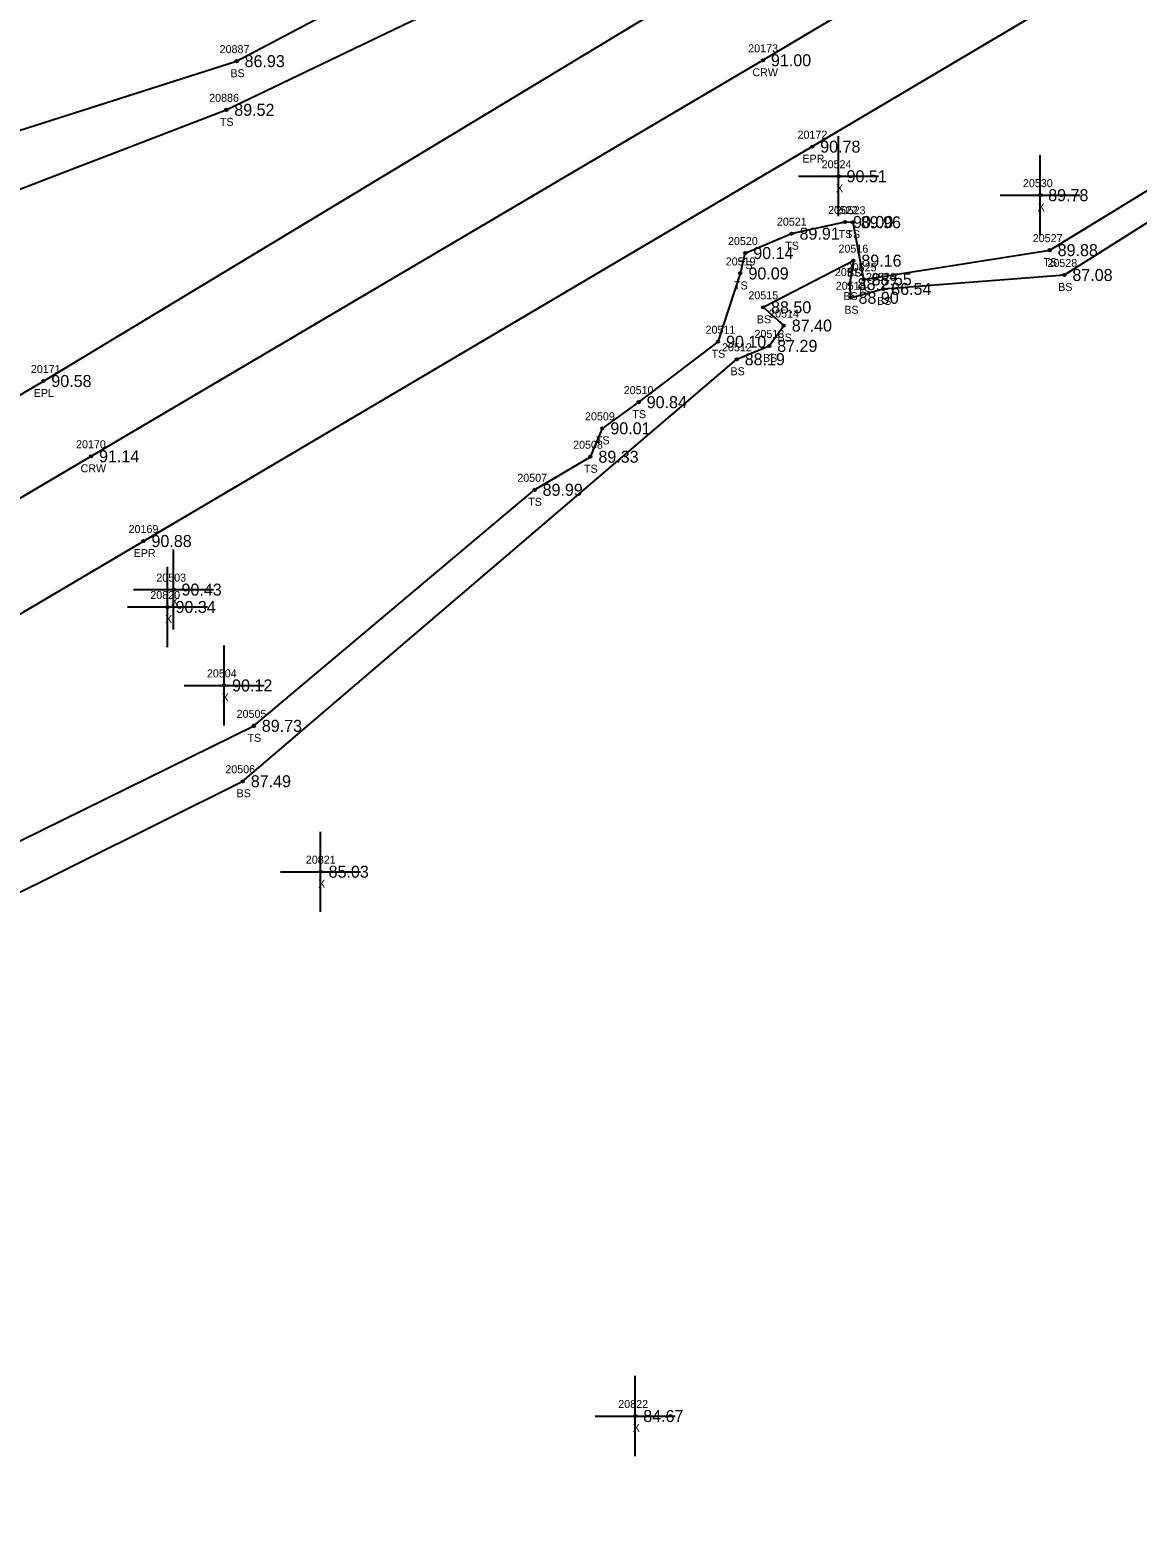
# Model space of a CAD drawing. Extents: x 2530197 to 2532051, y 935230 to 936631.
# Drawn here: x 2531374.5 to 2531512.9, y 935982 to 936167.6 of the extents above; entities that cross this region are included whole.
import ezdxf

# ---------------------------------------------------------------- set-up
doc = ezdxf.new("R2010")
doc.units = 0
for name, color, linetype in [('RD_DTM_BkLn1', 7, 'Continuous'), ('RD_DTM_BkLn2', 7, 'Continuous'), ('RD_DTM_BkLn_txCode', 7, 'Continuous'), ('RD_EX_Misc', 7, 'Continuous'), ('RD_EX_Misc_txCode', 7, 'Continuous'), ('RD_EX_Road', 7, 'Continuous'), ('RD_EX_Road_txCode', 7, 'Continuous'), ('RD_EX_TX_Misc_ELEV', 7, 'Continuous'), ('RD_EX_TX_Road_ELEV', 7, 'Continuous'), ('RD_HC_Survey_ELEV', 7, 'Continuous'), ('RD_HC_Survey_txCode', 7, 'Continuous'), ('RD_SMD_Locator', 7, 'Continuous')]:
    doc.layers.add(name, color=color, linetype=linetype)

msp = doc.modelspace()

# ---------------------------------------------------------------- linework, layer by layer
at = {"layer": 'RD_DTM_BkLn1'}
msp.add_lwpolyline([(2531175.16, 935992.09), (2531214.08, 936014.93), (2531297.2, 936064.16), (2531382.2, 936114.3), (2531466.12, 936163.77), (2531548.89, 936212.96), (2531632.55, 936261.89), (2531678, 936289.19), (2531722.34, 936315.93), (2531754.26, 936342.49), (2531759.78, 936349.83), (2531772.77, 936373.29), (2531778.96, 936389.71), (2531793.78, 936438.29), (2531813.65, 936511.36), (2531832.39, 936582.88)], dxfattribs=at)
at = {"layer": 'RD_DTM_BkLn2'}
for points in [[(2531232.8, 936067.46), (2531281.18, 936092.01), (2531356.28, 936135.72), (2531362.71, 936151.65), (2531400.38, 936163.66), (2531430.03, 936179.35), (2531446.05, 936177.07), (2531452.65, 936188.16), (2531481.32, 936210.45), (2531494.44, 936219.29)], [(2531229.61, 936049.23), (2531287.21, 936081.23), (2531360.99, 936124.94), (2531368.39, 936145.81), (2531399.09, 936157.58), (2531431.15, 936172.97), (2531448.86, 936171.41), (2531455.43, 936183.06), (2531483.94, 936207.52), (2531496.93, 936216.06)], [(2531295.18, 936026.12), (2531312.3, 936036.23), (2531402.53, 936080.62), (2531437.6, 936110.11), (2531444.57, 936114.24), (2531446.06, 936117.79), (2531450.6, 936121.06), (2531460.51, 936128.61), (2531463.31, 936137.14), (2531463.91, 936139.69), (2531469.69, 936142.11), (2531476.37, 936143.57), (2531477.33, 936143.53), (2531478.69, 936136.4), (2531501.93, 936140.05), (2531521.67, 936152.11)], [(2531295.18, 936026.12), (2531317.6, 936032.12), (2531401.15, 936073.7), (2531462.84, 936126.42), (2531466.9, 936128.09), (2531468.72, 936130.63), (2531466.13, 936132.91), (2531477.41, 936138.74), (2531476.94, 936135.81), (2531477.06, 936134.1), (2531481.14, 936135.21), (2531503.77, 936136.95), (2531524.91, 936150.29)]]:
    msp.add_lwpolyline(points, dxfattribs=at)
at = {"layer": 'RD_EX_Misc'}
for p, q in [((2531475.56, 936144.28), (2531475.56, 936154.28)), ((2531500.75, 936141.92), (2531500.75, 936151.92)), ((2531470.56, 936149.28), (2531480.56, 936149.28)), ((2531495.75, 936146.92), (2531505.75, 936146.92)), ((2531392.5, 936092.64), (2531392.5, 936102.64)), ((2531391.75, 936090.47), (2531391.75, 936100.47)), ((2531387.5, 936097.64), (2531397.5, 936097.64)), ((2531386.75, 936095.47), (2531396.75, 936095.47)), ((2531398.82, 936080.67), (2531398.82, 936090.67)), ((2531393.82, 936085.67), (2531403.82, 936085.67)), ((2531410.87, 936057.4), (2531410.87, 936067.4)), ((2531405.87, 936062.4), (2531415.87, 936062.4)), ((2531450.17, 935989.4), (2531450.17, 935999.4)), ((2531445.17, 935994.4), (2531455.17, 935994.4))]:
    msp.add_line(p, q, dxfattribs=at)
at = {"layer": 'RD_EX_Road'}
for points in [[(2531169.65, 936000.77), (2531208.79, 936024.95), (2531292.04, 936074.02), (2531376.24, 936123.7), (2531460.37, 936174.49), (2531542.92, 936223.44), (2531626.67, 936270.85), (2531672.4, 936298.39), (2531714.28, 936327.21), (2531747.19, 936360.45), (2531761.42, 936377.32), (2531773.11, 936411.11), (2531782.2, 936441.65), (2531803.17, 936514.76), (2531820.28, 936585.8)], [(2531180.82, 935982), (2531220.82, 936004.21), (2531303.54, 936053.39), (2531388.75, 936103.71), (2531472.27, 936152.98), (2531554.79, 936201.9), (2531638.11, 936250.92), (2531683.19, 936278.28), (2531730.37, 936304.55), (2531771.5, 936341.26), (2531788.67, 936375.53), (2531805.57, 936434.84), (2531825.53, 936508.74), (2531844.13, 936579.65)]]:
    msp.add_lwpolyline(points, dxfattribs=at)
at = {"layer": 'RD_SMD_Locator'}
for centre in [(2531400.38, 936163.66), (2531466.12, 936163.77), (2531399.09, 936157.58), (2531472.27, 936152.98), (2531475.56, 936149.28), (2531500.75, 936146.92), (2531476.37, 936143.57), (2531477.33, 936143.53), (2531469.69, 936142.11), (2531463.91, 936139.69), (2531477.41, 936138.74), (2531501.93, 936140.05), (2531463.31, 936137.14), (2531503.77, 936136.95), (2531476.94, 936135.81), (2531478.69, 936136.4), (2531481.14, 936135.21), (2531466.13, 936132.91), (2531477.06, 936134.1), (2531468.72, 936130.63), (2531460.51, 936128.61), (2531466.9, 936128.09), (2531462.84, 936126.42), (2531376.24, 936123.7), (2531450.6, 936121.06), (2531446.06, 936117.79), (2531382.2, 936114.3), (2531444.57, 936114.24), (2531437.6, 936110.11), (2531388.75, 936103.71), (2531392.5, 936097.64), (2531391.75, 936095.47), (2531398.82, 936085.67), (2531402.53, 936080.62), (2531401.15, 936073.7), (2531410.87, 936062.4), (2531450.17, 935994.4)]:
    msp.add_circle(centre, 0.15, dxfattribs=at)

# ---------------------------------------------------------------- texts
at = {"layer": 'RD_DTM_BkLn_txCode'}
for s, p in [('20887', (2531398.26, 936164.66)), ('BS', (2531399.6, 936161.66)), ('20886', (2531396.95, 936158.58)), ('TS', (2531398.29, 936155.58)), ('20522', (2531474.25, 936144.57)), ('20523', (2531475.21, 936144.53)), ('20521', (2531467.86, 936143.11)), ('TS', (2531475.58, 936141.57)), ('TS', (2531476.54, 936141.53)), ('20520', (2531461.75, 936140.69)), ('TS', (2531468.9, 936140.11)), ('20516', (2531475.55, 936139.74)), ('20527', (2531499.82, 936141.05)), ('20519', (2531461.47, 936138.14)), ('TS', (2531463.11, 936137.69)), ('TS', (2531501.14, 936138.05)), ('20528', (2531501.65, 936137.95)), ('20517', (2531475.1, 936136.81)), ('20525', (2531476.58, 936137.4)), ('BS', (2531476.63, 936136.74)), ('20526', (2531478.99, 936136.21)), ('TS', (2531462.51, 936135.14)), ('20515', (2531464.3, 936133.91)), ('20518', (2531475.22, 936135.1)), ('TS', (2531477.9, 936134.4)), ('BS', (2531502.99, 936134.95)), ('BS', (2531476.16, 936133.81)), ('BS', (2531476.28, 936132.1)), ('BS', (2531480.36, 936133.21)), ('BS', (2531465.35, 936130.91)), ('20514', (2531466.89, 936131.63)), ('20511', (2531458.95, 936129.61)), ('20513', (2531465.06, 936129.09)), ('BS', (2531467.94, 936128.63)), ('TS', (2531459.71, 936126.61)), ('20512', (2531461.01, 936127.42)), ('BS', (2531466.12, 936126.09)), ('BS', (2531462.06, 936124.42)), ('20510', (2531448.73, 936122.06)), ('TS', (2531449.81, 936119.06)), ('20509', (2531443.9, 936118.79)), ('TS', (2531445.26, 936115.79)), ('20508', (2531442.41, 936115.24)), ('TS', (2531443.77, 936112.24)), ('20507', (2531435.44, 936111.11)), ('TS', (2531436.8, 936108.11)), ('20505', (2531400.38, 936081.62)), ('TS', (2531401.74, 936078.62)), ('20506', (2531398.97, 936074.7)), ('BS', (2531400.38, 936071.7))]:
    msp.add_text(s, height=1, dxfattribs=at).set_placement(p)
at = {"layer": 'RD_EX_Misc_txCode'}
for s, p in [('20524', (2531473.45, 936150.28)), ('X', (2531475.25, 936147.28)), ('20530', (2531498.59, 936147.92)), ('X', (2531500.43, 936144.92)), ('20503', (2531390.35, 936098.64)), ('20820', (2531389.6, 936096.47)), ('X', (2531392.19, 936095.64)), ('X', (2531391.44, 936093.47)), ('20504', (2531396.67, 936086.67)), ('X', (2531398.51, 936083.67)), ('20821', (2531409.03, 936063.4)), ('X', (2531410.55, 936060.4)), ('20822', (2531448.05, 935995.4)), ('X', (2531449.85, 935992.4))]:
    msp.add_text(s, height=1, dxfattribs=at).set_placement(p)
at = {"layer": 'RD_EX_Road_txCode'}
for s, p in [('20172', (2531470.44, 936153.98)), ('EPR', (2531471.04, 936150.98)), ('20171', (2531374.68, 936124.7)), ('EPL', (2531375.03, 936121.7)), ('20169', (2531386.89, 936104.71)), ('EPR', (2531387.52, 936101.71))]:
    msp.add_text(s, height=1, dxfattribs=at).set_placement(p)
at = {"layer": 'RD_EX_TX_Misc_ELEV'}
for s, p in [('86.93', (2531401.38, 936162.91)), ('89.52', (2531400.09, 936156.83)), ('90.51', (2531476.56, 936148.53)), ('89.78', (2531501.75, 936146.17)), ('90.00', (2531477.37, 936142.82)), ('89.96', (2531478.33, 936142.78)), ('89.91', (2531470.69, 936141.36)), ('89.88', (2531502.93, 936139.3)), ('90.14', (2531464.91, 936138.94)), ('89.16', (2531478.41, 936137.99)), ('90.09', (2531464.31, 936136.39)), ('88.55', (2531479.69, 936135.65)), ('87.08', (2531504.77, 936136.2)), ('88.27', (2531477.94, 936135.06)), ('86.54', (2531482.14, 936134.46)), ('88.50', (2531467.13, 936132.16)), ('88.90', (2531478.06, 936133.35)), ('87.40', (2531469.72, 936129.88)), ('90.10', (2531461.51, 936127.86)), ('87.29', (2531467.9, 936127.34)), ('88.19', (2531463.84, 936125.67)), ('90.84', (2531451.6, 936120.31)), ('90.01', (2531447.06, 936117.04)), ('89.33', (2531445.57, 936113.49)), ('89.99', (2531438.6, 936109.36)), ('90.43', (2531393.5, 936096.89)), ('90.34', (2531392.75, 936094.72)), ('90.12', (2531399.82, 936084.92)), ('89.73', (2531403.53, 936079.87)), ('87.49', (2531402.15, 936072.95)), ('85.03', (2531411.87, 936061.65)), ('84.67', (2531451.17, 935993.65))]:
    msp.add_text(s, height=1.5, dxfattribs=at).set_placement(p)
at = {"layer": 'RD_EX_TX_Road_ELEV'}
for s, p in [('90.78', (2531473.27, 936152.23)), ('90.58', (2531377.24, 936122.95)), ('90.88', (2531389.75, 936102.96))]:
    msp.add_text(s, height=1.5, dxfattribs=at).set_placement(p)
at = {"layer": 'RD_HC_Survey_ELEV'}
for s, p in [('91.00', (2531467.12, 936163.02)), ('91.14', (2531383.2, 936113.55))]:
    msp.add_text(s, height=1.5, dxfattribs=at).set_placement(p)
at = {"layer": 'RD_HC_Survey_txCode'}
for s, p in [('20173', (2531464.28, 936164.77)), ('CRW', (2531464.8, 936161.77)), ('20170', (2531380.33, 936115.3)), ('CRW', (2531380.89, 936112.3))]:
    msp.add_text(s, height=1, dxfattribs=at).set_placement(p)

doc.saveas('drawing.dxf')
